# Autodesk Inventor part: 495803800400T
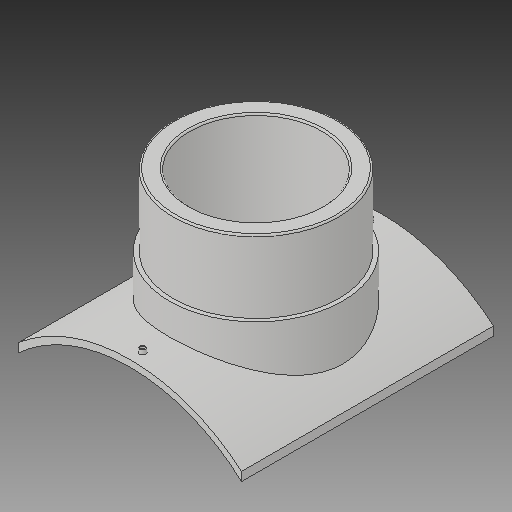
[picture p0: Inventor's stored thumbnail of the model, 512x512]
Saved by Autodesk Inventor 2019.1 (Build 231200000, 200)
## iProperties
Created: 2017-10
Part Number: 495803800400T
Material: Generic
Description: PLASSON BRANCH SADDLE  800x400
Document SubType Name: Modeling
Designer: KIM
Mass: 2754.05 g
Surface Area: 3037.44 cm^2
Volume: 2754.05 cm^3
Density: 1 g/cm^3
Appearance: Default
Author: KIM
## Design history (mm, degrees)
derived "495803.ipt"
feature "Solid1::495803.ipt"
tag "TaggingFeature1"
body "Solid1"
other parameters: "d1" = 16, "d4" = 0, "d12" = 425.6, "d13" = 14, "d14" = 274.5, "d16" = 5 deg, "d18" = 4, "d19" = 14, "d20" = 0, "d21" = 3, "d22" = 0, "d23" = 666, "d25" = 16, "d28" = 0, "d29" = 9.6, "d31" = 0, "d32" = 125, "d33" = 0, "d34" = 8, "d37" = 175, "d38" = 0, "d39" = 4, "x_" = 16, "D_" = 16
